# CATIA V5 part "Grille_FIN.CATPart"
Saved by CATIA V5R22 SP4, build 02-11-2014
Part number: Grille
Material "ﾌﾟﾗｽﾃｨｯｸ": density 1200 kg/m3, Young's modulus 2.2e+09 Pa, Poisson ratio 0.38, thermal expansion 6.84e-05 1/K
Bounding box of the stored display mesh (mm): x -185 to -100.001, y -313 to 313, z 227 to 413
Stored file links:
  C:\DATA\Car_ASSY\教育モデル\4_SUR\Grille_FIN.CATPart
  D:\Car_ASSY\Main_Car_body.CATPart
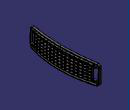
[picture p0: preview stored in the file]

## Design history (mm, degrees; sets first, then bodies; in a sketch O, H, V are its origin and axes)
Set1 "Front"
  Point1: type OnPlane, Support zx-plane, H 1100, V 300, Direction (-1, 0, 0)
  Circle1: type CtrRad, Start 169, End 188, Center Point1, Support zx-plane, Radius 1000, FirstDirection (-1, 0, 0)
  Circle2: type CtrRad, Start -27.2045, End 28.1939, Center Point1, Support xy-plane, Radius 1000, FirstDirection (1, 0, 0)
  Sweep1: type Unspec, Profile Circle1, Guide Circle2
Set2 "Danmen"
  Intersect1: ToIntersect1 Sweep1, ToIntersect2 Body3
  Plane1: type Offset, RefPlane yz-plane, Offset -185
Body1 (main body)
  Body2
    Pad1: profile Intersect1, direction along X axis, length -20
    Fillet1: radius 2, on face of Pad1
    Sketch1 on Plane1, origin (-185, 0, 0), H (0, 1, 0), V (0, 0, 1)
      circle A1 centre (-280, 370) radius 6
      circle A2 centre (-280, 260) radius 6
      circle A3 centre (280, 370) radius 6
      circle A4 centre (280, 260) radius 6
      circle A5 centre (-280, 370) radius 9
      point P1 (-280, 370)
      circle A6 centre (-280, 260) radius 9
      point P2 (-280, 260)
      circle A7 centre (280, 260) radius 9
      point P3 (280, 260)
      circle A8 centre (280, 370) radius 9
      point P4 (280, 370)
      radius A5 = 9
      radius A6 = 9
      radius A7 = 9
      radius A8 = 9
      distance P4 V = 280
      distance H P4 = 370
      radius A3 = 6
      distance P3 P4 = 110
      distance V P3 = 280
      radius A4 = 6
      radius A2 = 6
      radius A1 = 6
      distance P1 V = 280
      distance P2 V = 280
      distance H P2 = 260
      distance P2 P1 = 110
      concentricity: P1 A1, P2 A2, P3 A4, P4 A3
    Pad2: profile Sketch1, direction (-1, 0, 0), up to the existing solid (limit type 2)
  Add1: tool Body2
Body3
  Sketch2 on yz-plane, origin (0, 0, 0), H (0, 1, 0), V (0, 0, 1)
    point P1 (0.0002, 410)
    construction line L1 (0.0002, 410) -> (310, 410)
    point P2 (310, 410)
    line L2 (310, 372.6426) -> (310, 250)
    point P3 (310, 230)
    line L3 (290, 230) -> (0, 230)
    point P4 (0, 230)
    circle A1 centre (280, 370) radius 8
    circle A2 centre (280, 260) radius 8
    spline S1 through (0.0002, 410) (184.2802, 403.8794) (310, 390)
    arc A3 centre (290, 250) radius 20 from (290, 230) to (310, 250) ccw
    point P5 (290, 230)
    point P6 (310, 250)
    arc A4 centre (290, 372.6426) radius 20 from (292.7155, 392.4574) to (310, 372.6426) cw
    point P8 (292.7155, 392.4574)
    point P9 (310, 372.6426)
    offsetcurve C1
    point P11 (0.0002, 390)
    point P12 (290.0001, 372.6425)
    construction line L4 (0.0002, 410) -> (0.0002, 390)
    point P13 (0.0002, 410)
    construction line L5 through (0.0002, 410) direction (-1, 0)
    construction line L6 (292.7155, 392.4574) -> (290.0001, 372.6425)
    construction line L7 through (292.7155, 392.4574) direction (0.9907, -0.1358)
    line L8 (260, 376.4843) -> (260, 255)
    point P14 (257.373, 372.6426)
    point P15 (257.373, 250)
    construction line L9 (310, 372.6426) -> (257.373, 372.6426)
    construction line L10 (310, 250) -> (257.373, 250)
    line L11 (255, 250) -> (0, 250)
    point P16 (290, 250)
    point P17 (0, 250)
    construction line L12 (290, 230) -> (290, 250)
    construction line L13 (0, 230) -> (0, 250)
    point P18 (260, 376.4843)
    point P19 (260, 250)
    line L14 (272, 370) -> (260, 370)
    point P20 (272, 370)
    point P21 (260, 370)
    line L15 (288, 370) -> (310, 370)
    point P22 (288, 370)
    point P23 (310, 370)
    line L16 (288, 260) -> (310, 260)
    point P24 (288, 260)
    point P25 (310, 260)
    line L17 (272, 260) -> (260, 260)
    point P26 (272, 260)
    point P27 (260, 260)
    line L18 (260, 275) -> (0, 275)
    point P28 (260, 275)
    point P29 (0, 275)
    construction line L19 (260, 250) -> (260, 275)
    construction line L20 (0, 250) -> (0, 275)
    line L21 (260, 300) -> (0, 300)
    point P30 (260, 300)
    point P31 (0, 300)
    construction line L22 (260, 275) -> (260, 300)
    construction line L23 (0, 275) -> (0, 300)
    line L24 (260, 325) -> (0, 325)
    point P32 (260, 325)
    point P33 (0, 325)
    construction line L25 (260, 300) -> (260, 325)
    construction line L26 (0, 300) -> (0, 325)
    line L27 (260, 350) -> (0, 350)
    point P34 (260, 350)
    point P35 (0, 350)
    construction line L28 (260, 325) -> (260, 350)
    construction line L29 (0, 325) -> (0, 350)
    line L30 (260, 375) -> (0, 375)
    point P36 (260, 375)
    point P37 (0, 375)
    construction line L31 (260, 350) -> (260, 375)
    construction line L32 (0, 350) -> (0, 375)
    arc A5 centre (255, 255) radius 5 from (260, 255) to (255, 250) cw
    point P38 (260, 255)
    point P39 (255, 250)
    line L33 (17.5, 250) -> (17.5, 389.9532)
    point P41 (17.5, 250)
    point P42 (17.5, 389.9532)
    line L34 (52.5, 250) -> (52.5, 389.5709)
    point P43 (52.5, 250)
    point P44 (52.5, 389.5709)
    line L35 (87.5, 250) -> (87.5, 388.769)
    point P45 (87.5, 250)
    point P46 (87.5, 388.769)
    line L36 (122.5, 250) -> (122.5, 387.4859)
    point P47 (122.5, 250)
    point P48 (122.5, 387.4859)
    line L37 (157.5, 250) -> (157.5, 385.6484)
    point P49 (157.5, 250)
    point P50 (157.5, 385.6484)
    line L38 (192.5, 250) -> (192.5, 383.1854)
    point P51 (192.5, 250)
    point P52 (192.5, 383.1854)
    line L39 (227.5, 250) -> (227.5, 380.0419)
    point P53 (227.5, 250)
    point P54 (227.5, 380.0419)
    point P55 (-0.0002, 410)
    point P56 (-310, 410)
    construction line L40 (-0.0002, 410) -> (-310, 410)
    point P57 (-310, 230)
    point P58 (0, 230)
    point P59 (-290, 230)
    point P60 (-310, 250)
    point P62 (-292.7155, 392.4574)
    point P63 (-310, 372.6426)
    point P65 (-0.0002, 390)
    point P66 (-290.0001, 372.6425)
    point P67 (-257.373, 372.6426)
    point P68 (-257.373, 250)
    point P69 (-290, 250)
    point P70 (0, 250)
    point P71 (-260, 376.4843)
    point P72 (-260, 250)
    point P73 (-272, 370)
    point P74 (-260, 370)
    point P75 (-288, 370)
    point P76 (-310, 370)
    point P77 (-288, 260)
    point P78 (-310, 260)
    point P79 (-272, 260)
    point P80 (-260, 260)
    point P81 (-260, 275)
    point P82 (0, 275)
    point P83 (-260, 300)
    point P84 (0, 300)
    point P85 (-260, 325)
    point P86 (0, 325)
    point P87 (-260, 350)
    point P88 (0, 350)
    point P89 (-260, 375)
    point P90 (0, 375)
    point P91 (-260, 255)
    point P92 (-255, 250)
    point P94 (-17.5, 250)
    point P95 (-17.5, 389.9532)
    point P96 (-52.5, 250)
    point P97 (-52.5, 389.5709)
    point P98 (-87.5, 250)
    point P99 (-87.5, 388.769)
    point P100 (-122.5, 250)
    point P101 (-122.5, 387.4859)
    point P102 (-157.5, 250)
    point P103 (-157.5, 385.6484)
    point P104 (-192.5, 250)
    point P105 (-192.5, 383.1854)
    point P106 (-227.5, 250)
    point P107 (-227.5, 380.0419)
    line L41 (-310, 372.6426) -> (-310, 250)
    line L42 (-290, 230) -> (0, 230)
    circle A6 centre (-280, 370) radius 8
    circle A7 centre (-280, 260) radius 8
    spline S2 through (-0.0002, 410) (-184.2802, 403.8794) (-310, 390)
    arc A8 centre (-290, 250) radius 20 from (-290, 230) to (-310, 250) cw
    arc A9 centre (-290, 372.6426) radius 20 from (-292.7155, 392.4574) to (-310, 372.6426) ccw
    offsetcurve C2
    line L43 (-260, 376.4843) -> (-260, 255)
    line L44 (-255, 250) -> (0, 250)
    line L45 (-272, 370) -> (-260, 370)
    line L46 (-288, 370) -> (-310, 370)
    line L47 (-288, 260) -> (-310, 260)
    line L48 (-272, 260) -> (-260, 260)
    line L49 (-260, 275) -> (0, 275)
    line L50 (-260, 300) -> (0, 300)
    line L51 (-260, 325) -> (0, 325)
    line L52 (-260, 350) -> (0, 350)
    line L53 (-260, 375) -> (0, 375)
    arc A10 centre (-255, 255) radius 5 from (-260, 255) to (-255, 250) ccw
    line L54 (-17.5, 250) -> (-17.5, 389.9532)
    line L55 (-52.5, 250) -> (-52.5, 389.5709)
    line L56 (-87.5, 250) -> (-87.5, 388.769)
    line L57 (-122.5, 250) -> (-122.5, 387.4859)
    line L58 (-157.5, 250) -> (-157.5, 385.6484)
    line L59 (-192.5, 250) -> (-192.5, 383.1854)
    line L60 (-227.5, 250) -> (-227.5, 380.0419)
    point P108 (0.0002, 410)
    point P109 (310, 390)
    point P110 (184.2802, 403.8794)
    point P111 (-0.0002, 410)
    point P112 (-310, 390)
    point P113 (-184.2802, 403.8794)
    distance H L3 = 230
    distance L2 V = 310
    distance P109 L1 = 20
    distance P2 P3 = 180
    distance V P110 = 184.2802
    distance P110 P109 V = 13.8794
    distance P108 P4 = 180
    radius A3 = 20
    radius A4 = 20
    distance L2 L8 = 50
    distance L3 L11 = 20
    distance L16 L3 = 30
    distance L15 L16 = 110
    distance A1 L15 = 8
    distance A1 L15 = 8
    distance A1 L2 = 38
    distance A2 L16 = 8
    distance A2 L16 = 8
    distance L2 A2 = 38
    distance L11 L18 = 25
    distance L18 L21 = 25
    distance L21 L24 = 25
    distance L24 L27 = 25
    distance L27 L30 = 25
    radius A5 = 5
    distance V L33 = 17.5
    distance L33 L34 = 35
    distance L34 L35 = 35
    distance L35 L36 = 35
    distance L36 L37 = 35
    distance L37 L38 = 35
    distance L38 L39 = 35
    horizontal: L1 H, L3 H, L14 H, L15 H, L16 H, L17 H
    vertical: L2 V, L33 V, L34 V, L35 V, L36 V, L37 V, L38 V, L39 V
    coincidence: P4 V, P108 P1, P109 L2, P2 L2, L3 P3, L2 P3, P108 P13, P12 C1, P16 L11, P20 A1, P21 L8, P22 L14, P22 A1, P23 L2, P24 A2, P25 L2, P26 L16, P26 A2, P27 L8, L8 P19, L11 P19, P41 L11, P42 C1, P43 L11, P44 C1, P45 L11, P46 C1, P47 L11, P48 C1, P49 L11, P50 C1, P51 L11, P52 C1, P53 L11, P54 C1, P4 P58, P17 P70, P29 P82, P31 P84, P33 P86, P35 P88, P37 P90
    tangency: A3 L3, A3 L2, A4 S1, A4 L2, L5 S1, L7 S1, A5 L8, A5 L11
    perpendicularity: L4 L5, L6 L7, L9 L2, L9 L8, L10 L2, L10 L8, L12 L3, L12 L11, L13 L3, L13 L11, L19 L11, L19 L18, L20 L11, L20 L18, L22 L18, L22 L21, L23 L18, L23 L21, L25 L21, L25 L24, L26 L21, L26 L24, L28 L24, L28 L27, L29 L24, L29 L27, L31 L27, L31 L30, L32 L27, L32 L30
    symmetry: P1 P55 V, P2 P56 V, L1 L40 V, P3 P57 V, P4 P58 V, P5 P59 V, P6 P60 V, P8 P62 V, P9 P63 V, P11 P65 V, P12 P66 V, P14 P67 V, P15 P68 V, P16 P69 V, P17 P70 V, P18 P71 V, P19 P72 V, P20 P73 V, P21 P74 V, P22 P75 V, P23 P76 V, P24 P77 V, P25 P78 V, P26 P79 V, P27 P80 V, P28 P81 V, P29 P82 V, P30 P83 V, P31 P84 V, P32 P85 V, P33 P86 V, P34 P87 V, P35 P88 V, P36 P89 V, P37 P90 V, P38 P91 V, P39 P92 V, P41 P94 V, P42 P95 V, P43 P96 V, P44 P97 V, P45 P98 V, P46 P99 V, P47 P100 V, P48 P101 V, P49 P102 V, P50 P103 V, P51 P104 V, P52 P105 V, P53 P106 V, P54 P107 V, L2 L41 V, L3 L42 V, A1 A6 V, A2 A7 V, S1 S2 V, A3 A8 V, A4 A9 V, C1 C2 V, L8 L43 V, L11 L44 V, L14 L45 V, L15 L46 V, L16 L47 V, L17 L48 V, L18 L49 V, L21 L50 V, L24 L51 V, L27 L52 V, L30 L53 V, A5 A10 V, L33 L54 V, L34 L55 V, L35 L56 V, L36 L57 V, L37 L58 V, L38 L59 V, L39 L60 V, P108 P111 V, P109 P112 V, P110 P113 V
  Pad3: profile Sketch2, direction (1, 0, 0), length -298, thin wall 6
